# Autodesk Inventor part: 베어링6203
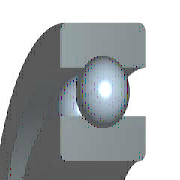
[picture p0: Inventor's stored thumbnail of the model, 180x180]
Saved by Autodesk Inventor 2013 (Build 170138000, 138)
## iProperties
IsCustomPart: 0
Company: 한국ATC센터
Created: 2014-12
Part Number: 베어링6203
Material: 강, 연강
Description: 깊은 그루브 볼 베어링
Document SubType Name: Modeling
Standard: KS B 2023
Designer: KYOUNG IL JANG
Standards Organization: KS
Language: ko-KR
Size Designation: 6203 - 17 x 40 x 12
Categories: <MemberInstance><Categories><Category DisplayName="샤프트 부품" InternalName="7f7aeb1f-a693-4053-b835-cee3144e0d98" Mnemonic="SHFT"><Category DisplayName="베어링" Inter
Density: 7.86 g/cm^3
Mass: 64.9809 g
Surface Area: 64.3582 cm^2
Volume: 8.26729 cm^3
Author: KYOUNG IL JANG
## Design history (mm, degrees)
sketch "스케치" dims "d0" = 5.98 (= -0.26 x WD + 0.26 x BD)
  geometry: L1 (3.01, 14.25)-(8.99, 14.25); L2 (6, 14.25)-(6, 11.26); L3 (6, 14.25)-(6, 17.24); L4 (3.778, 12.249)-(0, 12.249); L5 (0, 8.5)-(12, 8.5); L6 (3.778, 16.251)-(0, 16.251); L7 (0, 20)-(12, 20); L8 (12, 8.5)-(12, 12.249); L9 (8.222, 12.249)-(12, 12.249); L10 (8.222, 16.251)-(12, 16.251); L11 (12, 20)-(12, 16.251); L12 (-1.4, 0)-(8.4, 0) reference; L13 (0, -0.3)-(0, 5.3) reference
  constraints: 22 end point, 4 point on line, 2 collinear, 2 perpendicular, 2 symmetric about line, 1 midpoint, 1 parallel, 14 other
  dimensions: "d9" = 17 diameter of L5 L12 (= WD); "d11" = 40 diameter of L7 L12 (= BD); "d12" = 12 distance between parallel lines of L8 L13 (= KB); "d13" = 24.498 diameter of L9 L12 (= 0.326 x BD + 0.674 x WD)
revolve "본체" stored, may be unused: angle "d6" = 90 deg
revolve "볼" stored, may be unused: angle "d7" = 90 deg
pattern_circular "IDS_ARRAYBALL[SIMPL:T]" dims angle "d3" = 360 deg
body "Solid1"
fillet "모깎기1" dims "d1" = 0.6 (= KRS)
other parameters: "WD" = 17 [user parameter; used in 5 equation terms], "BD" = 40 [user parameter; used in 5 equation terms], "KB" = 12 [user parameter; used in 1 equation term], "KRS" = 0.6 [user parameter; used in 1 equation term], "d4" = 0, "d5" = 0, "d8" = 0, "d14" = 0, "d15" = 0, "BBA" = 0 [user parameter], "BC0" = 4750000 [user parameter], "BC" = 9560000 [user parameter], "WR" = 8.5 (= 0.5 x WD) [user parameter]
